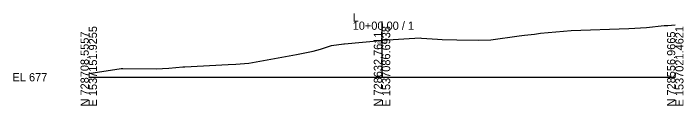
# Model space of a CAD drawing. Extents: x -26 to 1203, y -10 to 9522.
# Drawn here: x -25.7 to 202.8, y -9.7 to 21.8 of the extents above; entities that cross this region are included whole.
import ezdxf

# ---------------------------------------------------------------- set-up
doc = ezdxf.new("R2010")
doc.units = 0
for name, color, linetype in [('Default', 7, 'Continuous'), ('Exist Cross Section Cell', 7, 'Continuous'), ('Exist XS Center Line Elevation Label', 7, 'Continuous'), ('Exist XS Ground Line', 7, 'Continuous')]:
    doc.layers.add(name, color=color, linetype=linetype)

msp = doc.modelspace()

# ---------------------------------------------------------------- linework, layer by layer
at = {"layer": 'Exist Cross Section Cell'}
for p, q in [((100, 0), (100, 19)), ((0, 0), (100, 0)), ((100, 0), (200, 0))]:
    msp.add_line(p, q, dxfattribs=at)
at = {"layer": 'Exist XS Ground Line'}
msp.add_lwpolyline([(0, 1.33), (11.06, 2.97), (11.66, 3), (23.04, 2.92), (27.34, 3.13), (32.04, 3.55), (32.72, 3.55), (47.54, 4.33), (50.13, 4.48), (54.63, 4.83), (70.8, 7.79), (76.54, 8.85), (78.97, 9.61), (82.82, 10.84), (86.97, 11.42), (87.02, 11.42), (87.18, 11.44), (99.51, 12.59), (99.53, 12.59), (100, 12.62), (112.98, 13.4), (113.5, 13.36), (118.97, 12.98), (120.48, 12.94), (125.49, 12.82), (132.84, 12.71), (137.09, 12.78), (146.74, 14.1), (148.61, 14.36), (152.05, 14.75), (153.99, 15), (164.45, 15.94), (184.13, 16.64), (190.15, 16.95), (196.19, 17.62), (197.51, 17.69), (200, 17.84)], dxfattribs=at)

# ---------------------------------------------------------------- texts
at = {"layer": 'Default'}
msp.add_text('-', height=0.0001, dxfattribs=at).set_placement((0, 0))
msp.add_text('-', height=0.0001, dxfattribs=at).set_placement((0, 0))
msp.add_text('-', height=0.0001, dxfattribs=at).set_placement((0, 0))
at = {"layer": 'Exist Cross Section Cell'}
for s, p in [('L', (90, 19)), ('10+00.00 / 1', (90, 16.2)), ('EL 677', (-26, -1.4))]:
    msp.add_text(s, height=2.8, dxfattribs=at).set_placement(p)
for s, p in [('E 1537151.9255', (2.8, -10)), ('E 1537086.6938', (102.8, -10)), ('E 1537021.4621', (202.8, -10)), ('N 728708.5557', (0, -10)), ('N 728632.7611', (100, -10)), ('N 728556.9665', (200, -10))]:
    msp.add_text(s, height=2.8, rotation=90, dxfattribs=at).set_placement(p)
at = {"layer": 'Exist XS Center Line Elevation Label'}
msp.add_text('689.62', height=0.75, dxfattribs=at).set_placement((98.46, 11.36))

doc.saveas('drawing.dxf')
